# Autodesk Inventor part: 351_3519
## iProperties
Author: tomm
Created: 2002-01
Part Number: 351_3519
Document SubType Name: Modeling
Designer: tomm
Material: Steel, Mild
Control State: 0
Master: False
Checked Out: False
Last Check In Date: 2002-01-29
PropertySet Name: Design Tracking Control
Last Check In By: tomm
Shininess: 25.0
PropertySet Name: _Private Model Information
Density: 7.86
Volume: 0.5085807133092863
Area: 3.560886809357665
PropertySet Name: Model Information
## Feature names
1. Extrusion1
2. Extrusion2
3. Mirror1
4. Fillet1
5. Chamfer1
6. Revolution1
7. Mirror2
8. Fillet2
9. Base1
